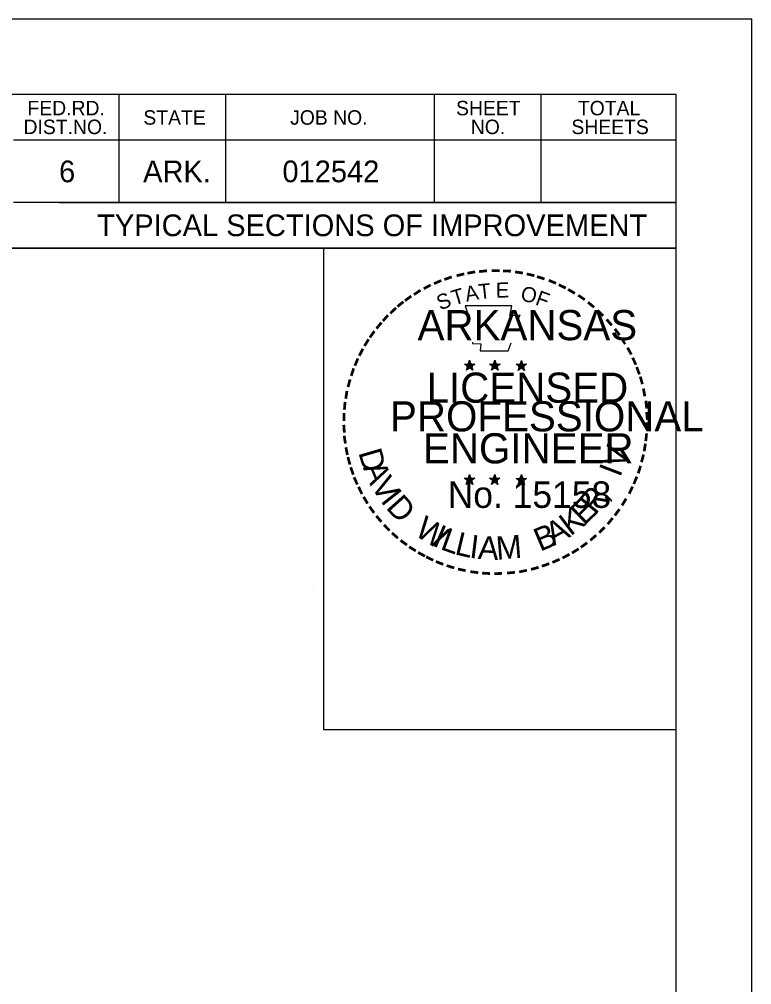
# Model space of a CAD drawing. Extents: x 34757 to 38214, y 51436 to 59430.
# Drawn here: x 36213.7 to 36456.6, y 55849.2 to 56169.6 of the extents above; entities that cross this region are included whole.
import ezdxf

# ---------------------------------------------------------------- set-up
doc = ezdxf.new("R2010")
doc.units = 0
for name, color, linetype in [('DSN_DRFT_Junk-No-Plot', 7, 'Continuous'), ('R_Border PE', 7, 'Continuous'), ('R_No Plot', 7, 'Continuous'), ('SHET_Annotations', 7, 'Continuous'), ('SHET_Border-Lines', 7, 'Continuous'), ('SHET_Border-Text', 7, 'Continuous'), ('SHET_Stamp-Prelim', 7, 'Continuous'), ('SHET_Stamp-Seal', 7, 'Continuous')]:
    doc.layers.add(name, color=color, linetype=linetype)

msp = doc.modelspace()

# ---------------------------------------------------------------- linework, layer by layer
at = {"layer": 'DSN_DRFT_Junk-No-Plot'}
msp.add_lwpolyline([(34756.64, 56169.61), (34756.64, 55069.61), (36456.64, 55069.61), (36456.64, 56169.61)], close=True, dxfattribs=at)
at = {"layer": 'R_Border PE'}
for p, q in [((36363.1, 56056.44), (36362.89, 56055.18)), ((36363.1, 56054.61), (36363.1, 56056.44)), ((36363.1, 56056.44), (36363.34, 56055.19)), ((36371.45, 56056.44), (36371.24, 56055.18)), ((36371.45, 56054.61), (36371.45, 56056.44)), ((36371.45, 56056.44), (36371.69, 56055.19)), ((36380.27, 56056.38), (36380.06, 56055.12)), ((36380.27, 56054.55), (36380.27, 56056.38)), ((36380.27, 56056.38), (36380.51, 56055.13)), ((36361.35, 56055.17), (36363.1, 56054.61)), ((36361.35, 56055.17), (36362.62, 56054.94)), ((36361.35, 56055.17), (36362.54, 56054.56)), ((36362.02, 56053.13), (36363.1, 56054.61)), ((36362.02, 56053.13), (36362.65, 56054.35)), ((36362.02, 56053.13), (36363.09, 56054.21)), ((36364.16, 56053.13), (36363.09, 56054.2)), ((36364.83, 56055.17), (36363.1, 56054.61)), ((36364.16, 56053.13), (36363.1, 56054.61)), ((36364.83, 56055.17), (36363.4, 56054.92)), ((36364.16, 56053.13), (36363.48, 56054.58)), ((36364.83, 56055.17), (36363.81, 56054.66)), ((36369.7, 56055.17), (36371.45, 56054.61)), ((36369.7, 56055.17), (36370.97, 56054.94)), ((36369.7, 56055.17), (36370.89, 56054.56)), ((36370.37, 56053.13), (36371.45, 56054.61)), ((36370.37, 56053.13), (36371, 56054.35)), ((36370.37, 56053.13), (36371.44, 56054.21)), ((36372.51, 56053.13), (36371.44, 56054.2)), ((36373.18, 56055.17), (36371.45, 56054.61)), ((36372.51, 56053.13), (36371.45, 56054.61)), ((36373.18, 56055.17), (36371.75, 56054.92)), ((36372.51, 56053.13), (36371.83, 56054.58)), ((36373.18, 56055.17), (36372.16, 56054.66)), ((36378.52, 56055.11), (36380.27, 56054.55)), ((36378.52, 56055.11), (36379.79, 56054.88)), ((36378.52, 56055.11), (36379.71, 56054.5)), ((36379.19, 56053.07), (36380.27, 56054.55)), ((36379.19, 56053.07), (36379.82, 56054.29)), ((36379.19, 56053.07), (36380.26, 56054.15)), ((36381.33, 56053.07), (36380.26, 56054.14)), ((36382, 56055.11), (36380.27, 56054.55)), ((36381.33, 56053.07), (36380.27, 56054.55)), ((36382, 56055.11), (36380.57, 56054.86)), ((36381.33, 56053.07), (36380.65, 56054.52)), ((36382, 56055.11), (36380.98, 56054.6)), ((36361.33, 56017.3), (36363.08, 56016.75)), ((36361.33, 56017.3), (36362.6, 56017.08)), ((36361.33, 56017.3), (36362.52, 56016.69)), ((36363.08, 56018.57), (36362.87, 56017.31)), ((36363.08, 56016.75), (36363.08, 56018.57)), ((36363.08, 56018.57), (36363.32, 56017.32)), ((36364.81, 56017.3), (36363.08, 56016.75)), ((36364.81, 56017.3), (36363.38, 56017.06)), ((36364.81, 56017.3), (36363.79, 56016.79)), ((36369.68, 56017.3), (36371.42, 56016.75)), ((36369.68, 56017.3), (36370.94, 56017.08)), ((36369.68, 56017.3), (36370.86, 56016.69)), ((36371.42, 56018.57), (36371.22, 56017.31)), ((36371.42, 56016.75), (36371.42, 56018.57)), ((36371.42, 56018.57), (36371.67, 56017.32)), ((36373.16, 56017.3), (36371.42, 56016.75)), ((36373.16, 56017.3), (36371.73, 56017.06)), ((36373.16, 56017.3), (36372.14, 56016.79)), ((36378.51, 56017.25), (36380.26, 56016.7)), ((36378.51, 56017.25), (36379.78, 56017.03)), ((36378.51, 56017.25), (36379.7, 56016.64)), ((36380.26, 56018.52), (36380.05, 56017.26)), ((36380.26, 56016.7), (36380.26, 56018.52)), ((36380.26, 56018.52), (36380.5, 56017.27)), ((36381.99, 56017.25), (36380.26, 56016.7)), ((36381.99, 56017.25), (36380.56, 56017.01)), ((36381.99, 56017.25), (36380.97, 56016.74)), ((36362, 56015.26), (36363.08, 56016.75)), ((36362, 56015.26), (36362.63, 56016.48)), ((36362, 56015.26), (36363.07, 56016.35)), ((36364.14, 56015.26), (36363.07, 56016.33)), ((36364.14, 56015.26), (36363.08, 56016.75)), ((36364.14, 56015.26), (36363.46, 56016.72)), ((36370.34, 56015.26), (36371.42, 56016.75)), ((36370.34, 56015.26), (36370.97, 56016.48)), ((36370.34, 56015.26), (36371.41, 56016.35)), ((36372.49, 56015.26), (36371.41, 56016.33)), ((36372.49, 56015.26), (36371.42, 56016.75)), ((36372.49, 56015.26), (36371.8, 56016.72)), ((36379.18, 56015.21), (36380.26, 56016.7)), ((36379.18, 56015.21), (36379.81, 56016.43)), ((36379.18, 56015.21), (36380.25, 56016.3)), ((36381.32, 56015.21), (36380.25, 56016.28)), ((36381.32, 56015.21), (36380.26, 56016.7)), ((36381.32, 56015.21), (36380.64, 56016.67))]:
    msp.add_line(p, q, dxfattribs=at)
for points in [[(36361.56, 56074.56), (36362.9, 56070.42)], [(36379.11, 56069.95), (36379.82, 56071.37), (36376.4, 56071.25), (36377.14, 56074.56), (36361.56, 56074.56)], [(36364.02, 56062.44), (36364.02, 56062.01), (36366.83, 56061.91), (36366.56, 56059.55), (36375.91, 56059.55), (36376.92, 56062.23)], [(36363.1, 56056.44), (36364.16, 56053.13), (36361.35, 56055.17), (36364.83, 56055.17), (36362.02, 56053.13), (36363.1, 56056.44)], [(36371.45, 56056.44), (36372.51, 56053.13), (36369.7, 56055.17), (36373.18, 56055.17), (36370.37, 56053.13), (36371.45, 56056.44)], [(36380.27, 56056.38), (36381.33, 56053.07), (36378.52, 56055.11), (36382, 56055.11), (36379.19, 56053.07), (36380.27, 56056.38)], [(36363.08, 56018.57), (36364.14, 56015.26), (36361.33, 56017.3), (36364.81, 56017.3), (36362, 56015.26), (36363.08, 56018.57)], [(36371.42, 56018.57), (36372.49, 56015.26), (36369.68, 56017.3), (36373.16, 56017.3), (36370.34, 56015.26), (36371.42, 56018.57)], [(36380.26, 56018.52), (36381.32, 56015.21), (36378.51, 56017.25), (36381.99, 56017.25), (36379.18, 56015.21), (36380.26, 56018.52)]]:
    msp.add_lwpolyline(points, dxfattribs=at)
for centre, radius in [((36363.09, 56054.61), 0.861), ((36371.44, 56054.61), 0.861), ((36380.26, 56054.55), 0.861), ((36363.09, 56054.61), 0.723), ((36363.09, 56054.61), 0.579), ((36363.09, 56054.61), 0.495), ((36363.09, 56054.61), 0.374), ((36363.09, 56054.61), 0.248), ((36363.09, 56054.61), 0.148), ((36371.44, 56054.61), 0.723), ((36371.44, 56054.61), 0.579), ((36371.44, 56054.61), 0.495), ((36371.44, 56054.61), 0.374), ((36371.44, 56054.61), 0.248), ((36371.44, 56054.61), 0.148), ((36380.26, 56054.55), 0.723), ((36380.26, 56054.55), 0.579), ((36380.26, 56054.55), 0.495), ((36380.26, 56054.55), 0.374), ((36380.26, 56054.55), 0.248), ((36380.26, 56054.55), 0.148), ((36363.07, 56016.74), 0.861), ((36363.07, 56016.74), 0.723), ((36363.07, 56016.74), 0.579), ((36363.07, 56016.74), 0.495), ((36363.07, 56016.74), 0.374), ((36363.07, 56016.74), 0.248), ((36371.42, 56016.74), 0.861), ((36371.42, 56016.74), 0.723), ((36371.42, 56016.74), 0.579), ((36371.42, 56016.74), 0.495), ((36371.42, 56016.74), 0.374), ((36371.42, 56016.74), 0.248), ((36380.25, 56016.69), 0.861), ((36380.25, 56016.69), 0.723), ((36380.25, 56016.69), 0.579), ((36380.25, 56016.69), 0.495), ((36380.25, 56016.69), 0.374), ((36380.25, 56016.69), 0.248), ((36363.07, 56016.74), 0.148), ((36371.42, 56016.74), 0.148), ((36380.25, 56016.69), 0.148)]:
    msp.add_circle(centre, radius, dxfattribs=at)
at = {"layer": 'R_No Plot'}
msp.add_line((36311.1, 55981.61), (36311.1, 55981.61), dxfattribs=at)
at = {"layer": 'SHET_Border-Lines'}
for p, q in [((36246.72, 56144.61), (36246.72, 56108.82)), ((36282.11, 56144.61), (36282.11, 56108.82)), ((36351.37, 56144.61), (36351.37, 56108.82)), ((36386.76, 56144.61), (36386.76, 56108.82)), ((36431.64, 56129.45), (36211.83, 56129.45)), ((36431.64, 56129.55), (36431.64, 56129.55)), ((36431.64, 56108.82), (36211.83, 56108.82)), ((36226.93, 56108.82), (36431.64, 56108.82)), ((36431.64, 56093.66), (36112.18, 56093.66))]:
    msp.add_line(p, q, dxfattribs=at)
for points in [[(34756.64, 55069.61), (36456.64, 55069.61), (36456.64, 56169.61), (34756.64, 56169.61)], [(34781.64, 55094.61), (36431.64, 55094.61), (36431.64, 56144.61), (34781.64, 56144.61)], [(36112.18, 56093.66), (36431.64, 56093.66), (36431.64, 56144.61), (36112.18, 56144.61)]]:
    msp.add_lwpolyline(points, close=True, dxfattribs=at)
at = {"layer": 'SHET_Stamp-Prelim'}
msp.add_lwpolyline([(36321.64, 56093.62), (36321.83, 56093.62), (36321.83, 56093.66), (36321.64, 56093.66)], close=True, dxfattribs=at)
at = {"layer": 'SHET_Stamp-Seal'}
msp.add_lwpolyline([(36314.63, 55933.94), (36431.64, 55933.94), (36431.64, 56093.66), (36314.63, 56093.66)], close=True, dxfattribs=at)

# ---------------------------------------------------------------- texts
at = {"layer": 'R_Border PE'}
for s, height, rotation, p in [('-', 8, 19.1761, (36355.29, 56080.19)), ('-', 8, 13.6302, (36359.04, 56081.4)), ('-', 8, 10.2193, (36362.43, 56082.21)), ('-', 8, 5.8968, (36366.08, 56082.76)), ('-', 8, 0.1862, (36369.94, 56083.12)), ('-', 8, 357.743, (36373.55, 56083.05)), ('-', 8, 352.1617, (36377.27, 56082.77)), ('-', 8, 347.2049, (36380.87, 56082.2)), ('-', 8, 342.3362, (36384.04, 56081.43)), ('-', 8, 28.7918, (36348.96, 56077.26)), ('-', 8, 24.3072, (36352.12, 56078.85)), ('A', 5, 11.2132, (36362.03, 56075.86)), ('T', 5, 6.0228, (36366.27, 56076.69)), ('E', 5, 0.8323, (36371.8, 56077.24)), ('-', 8, 337.8551, (36387.72, 56080.31)), ('-', 8, 334.1211, (36390.87, 56078.96)), ('-', 8, 36.2317, (36343.08, 56073.44)), ('-', 8, 34.0636, (36345.97, 56075.41)), ('S', 5, 21.594, (36353.33, 56072.95)), ('T', 5, 16.4036, (36357.9, 56074.6)), ('O', 5, 350.4515, (36379.82, 56076.19)), ('F', 5, 340.0707, (36384.59, 56075.05)), ('-', 8, 329.6409, (36393.77, 56077.54)), ('-', 8, 325.8627, (36396.98, 56075.74)), ('-', 8, 38.9507, (36340.7, 56071.55)), ('-', 8, 320.5297, (36400.03, 56073.61)), ('-', 8, 48.4231, (36336.3, 56067.07)), ('-', 8, 42.9622, (36338.54, 56069.46)), ('-', 8, 315.5786, (36403.03, 56071.17)), ('-', 8, 50.6142, (36334.28, 56064.64)), ('-', 8, 309.8797, (36405.87, 56068.42)), ('-', 8, 54.2325, (36332.22, 56061.81)), ('-', 8, 306.6522, (36408.5, 56065.41)), ('-', 8, 58.0706, (36330.59, 56059.17)), ('-', 7, 303.6753, (36410.93, 56062.57)), ('-', 8, 62.8713, (36329.03, 56056.1)), ('-', 8, 299.6684, (36412.52, 56059.53)), ('-', 8, 67.7743, (36327.73, 56053.05)), ('-', 8, 294.6628, (36414.14, 56056.47)), ('-', 8, 72.3945, (36326.64, 56049.9)), ('-', 8, 290.5728, (36415.43, 56053.59)), ('-', 8, 75.461, (36325.65, 56046.33)), ('-', 8, 285.1233, (36416.6, 56050.69)), ('-', 8, 81.2013, (36324.99, 56042.76)), ('-', 8, 280.5493, (36417.6, 56046.98)), ('-', 8, 85.1863, (36324.61, 56039.31)), ('-', 8, 276.5962, (36418.41, 56043.14)), ('-', 8, 89.0622, (36324.49, 56035.8)), ('-', 8, 274.3301, (36418.71, 56039.53)), ('-', 8, 94.1959, (36324.66, 56032.18)), ('-', 8, 269.9407, (36418.88, 56036.37)), ('-', 8, 98.9479, (36325.02, 56028.84)), ('-', 8, 263.5172, (36418.78, 56033.04)), ('-', 8, 101.7149, (36325.7, 56025.18)), ('D', 7.7, 286.2848, (36326.14, 56025.87)), ('V', 7.7, 72.6573, (36414.1, 56020.07)), ('-', 8, 260.9953, (36418.43, 56029.77)), ('-', 8, 105.4578, (36326.51, 56022.2)), ('-', 8, 255.7626, (36417.88, 56026.38)), ('-', 8, 109.0874, (36327.58, 56019.05)), ('A', 7.7, 292.7835, (36327.61, 56020.86)), ('I', 7.7, 69.0301, (36412.99, 56017.37)), ('-', 8, 252.8681, (36416.97, 56022.78)), ('-', 8, 114.0643, (36328.85, 56016.07)), ('V', 7.7, 300.7936, (36330.18, 56014.96)), ('-', 8, 247.8887, (36415.86, 56019.41)), ('-', 8, 115.7289, (36330.38, 56012.98)), ('I', 7.7, 308.3502, (36333.33, 56009.78)), ('R', 7.7, 50.3651, (36404.74, 56004.93)), ('-', 8, 244.6197, (36414.55, 56016.27)), ('-', 8, 120.4471, (36332.16, 56010.05)), ('D', 7.7, 311.9774, (36335.08, 56007.45)), ('E', 7.7, 44.0175, (36401.07, 56001.39)), (',', 7.7, 57.4684, (36408.36, 56009.34)), ('-', 8, 239.0712, (36412.58, 56012.51)), ('-', 8, 125.8934, (36334.18, 56007.24)), ('K', 7.7, 36.9143, (36396.53, 55997.94)), ('-', 8, 233.8452, (36410.57, 56009.24)), ('-', 8, 130.7181, (36336.49, 56004.48)), ('W', 7.7, 328.0731, (36344.48, 55998.62)), ('-', 8, 231.2538, (36408.42, 56006.41)), ('-', 8, 134.2238, (36339.07, 56001.76)), ('I', 7.7, 336.6877, (36350.41, 55995.07)), ('B', 7.7, 22.8589, (36386.46, 55992.88)), ('A', 7.7, 28.9042, (36390.94, 55994.75)), ('-', 8, 225.7653, (36406.02, 56003.59)), ('-', 8, 138.9338, (36341.7, 55999.44)), ('L', 7.7, 340.3149, (36353.06, 55993.85)), ('L', 7.7, 346.6625, (36357.86, 55992.13)), ('I', 7.7, 353.0101, (36362.82, 55990.95)), ('A', 7.7, 356.6373, (36365.7, 55990.52)), ('M', 7.7, 4.6473, (36372.13, 55990.23)), ('-', 8, 221.0851, (36403.41, 56001.05)), ('-', 8, 144.6463, (36344.48, 55997.41)), ('-', 8, 148.0898, (36347.28, 55995.55)), ('-', 8, 215.7363, (36400.67, 55998.69)), ('-', 8, 151.5704, (36350.18, 55993.93)), ('-', 8, 154.6002, (36352.79, 55992.69)), ('-', 8, 207.3568, (36395.21, 55995.02)), ('-', 8, 212.2491, (36398, 55996.75)), ('-', 8, 158.5612, (36355.91, 55991.42)), ('-', 8, 162.7983, (36359.34, 55990.36)), ('-', 8, 195.4743, (36385.61, 55990.85)), ('-', 8, 199.4643, (36388.93, 55992.04)), ('-', 8, 204.2516, (36392.09, 55993.43)), ('-', 8, 167.5555, (36362.92, 55989.54)), ('-', 8, 173.1155, (36366.78, 55988.99)), ('-', 8, 176.5183, (36370.52, 55988.72)), ('-', 8, 181.5918, (36374.24, 55988.82)), ('-', 8, 185.8167, (36378.28, 55989.2)), ('-', 8, 191.2858, (36381.96, 55989.86))]:
    msp.add_text(s, height=height, rotation=rotation, dxfattribs=at).set_placement(p)
for s, height, p in [('ARKANSAS', 10, (36345.82, 56063.12)), ('LICENSED', 10, (36348.81, 56042.37)), ('PROFESSIONAL', 10, (36336.69, 56032.85)), ('ENGINEER', 10, (36347.62, 56022.23)), ('No. 15158', 8.785, (36355.83, 56007.47)), ('AAMU', 0.0001, (36371.09, 55990.2))]:
    msp.add_text(s, height=height, dxfattribs=at).set_placement(p)
at = {"layer": 'SHET_Annotations'}
for s, p in [('6', (36226.93, 56115.54)), ('ARK.', (36254.8, 56115.54)), ('012542', (36301.01, 56115.54)), ('TYPICAL SECTIONS OF IMPROVEMENT', (36239.56, 56097.64))]:
    msp.add_text(s, height=7.2, dxfattribs=at).set_placement(p)
at = {"layer": 'SHET_Border-Text'}
for s, p in [('FED.RD.', (36216.44, 56137.75)), ('SHEET', (36358.59, 56137.75)), ('TOTAL', (36399, 56137.75)), ('STATE', (36254.89, 56134.63)), ('JOB NO.', (36303.56, 56134.63)), ('DIST.NO.', (36215.14, 56131.51)), ('NO.', (36363.48, 56131.51)), ('SHEETS', (36396.85, 56131.51))]:
    msp.add_text(s, height=4.8, dxfattribs=at).set_placement(p)
at = {"layer": 'SHET_Stamp-Prelim'}
for s, height, p in [('PRELIMINARY', 0.013, (36321.66, 56093.64)), ('SUBJECT TO REVISION', 0.009, (36321.67, 56093.63))]:
    msp.add_text(s, height=height, dxfattribs=at).set_placement(p)

doc.saveas('drawing.dxf')
